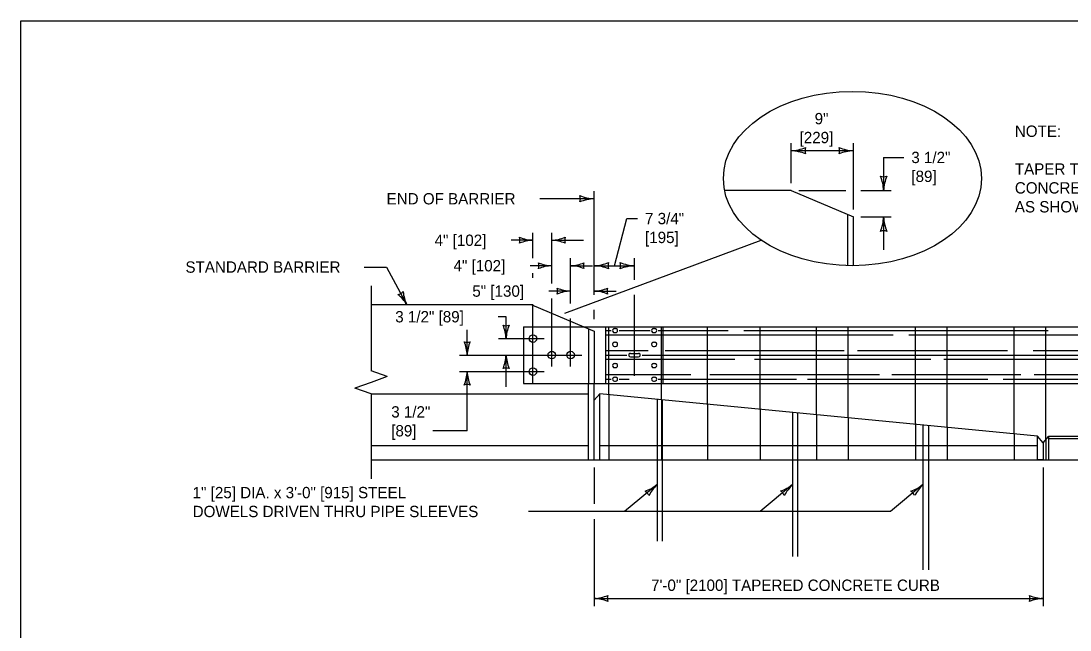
# Model space of a CAD drawing. Extents: x 49991.4 to 50021, y 49987.6 to 50011.4.
# Drawn here: x 49999.38 to 50004.93, y 49995.77 to 49999 of the extents above; entities that cross this region are included whole.
import ezdxf

# ---------------------------------------------------------------- set-up
doc = ezdxf.new("R2010")
doc.units = 0
for name, color, linetype in [('Level 1', 7, 'Continuous'), ('Level 2', 7, 'Continuous'), ('Level 3', 7, 'Continuous'), ('Level 4', 7, 'Continuous'), ('Level 5', 7, 'Continuous'), ('Level 6', 7, 'Continuous')]:
    doc.layers.add(name, color=color, linetype=linetype)

msp = doc.modelspace()

# ---------------------------------------------------------------- linework, layer by layer
at = {"layer": 'Level 1'}
for p, q in [((50003.4584, 49998.1012), (50003.1064, 49998.1012)), ((50003.4584, 49998.1012), (50003.788, 49997.9614)), ((50003.7578, 49997.7035), (50003.7578, 49997.9742)), ((50003.788, 49997.7033), (50003.788, 49997.9613)), ((50002.0873, 49997.4962), (50001.2358, 49997.4962)), ((50002.0873, 49997.4962), (50002.3616, 49997.3798)), ((50002.0422, 49997.3798), (50006.0658, 49997.3798)), ((50002.0422, 49997.3798), (50002.0422, 49997.0804)), ((50002.4775, 49997.0804), (50002.4775, 49997.3798)), ((50002.4775, 49997.3599), (50002.5055, 49997.3599)), ((50002.524, 49997.3709), (50002.5293, 49997.3709)), ((50002.5479, 49997.3599), (50002.7123, 49997.3599)), ((50002.7308, 49997.3709), (50002.7361, 49997.3709)), ((50002.7547, 49997.3599), (50003.1251, 49997.3599)), ((50003.209, 49997.3599), (50004.8191, 49997.3599)), ((50002.4775, 49997.3382), (50003.9979, 49997.3382)), ((50002.524, 49997.3489), (50002.5293, 49997.3489)), ((50002.7308, 49997.3489), (50002.7361, 49997.3489)), ((50004.082, 49997.3382), (50005.5076, 49997.3382)), ((50002.4775, 49997.2548), (50002.7015, 49997.2548)), ((50002.524, 49997.2982), (50002.5293, 49997.2982)), ((50002.524, 49997.2762), (50002.5293, 49997.2762)), ((50002.7308, 49997.2982), (50002.7361, 49997.2982)), ((50002.7308, 49997.2762), (50002.7361, 49997.2762)), ((50002.792, 49997.2548), (50003.7392, 49997.2548)), ((50003.8104, 49997.2548), (50004.6025, 49997.2548)), ((50004.7382, 49997.2548), (50005.7177, 49997.2548)), ((50002.4775, 49997.2301), (50002.5891, 49997.2301)), ((50002.4775, 49997.2083), (50003.1606, 49997.2083)), ((50002.6083, 49997.2392), (50002.6509, 49997.2392)), ((50002.6083, 49997.221), (50002.6509, 49997.221)), ((50002.67, 49997.2301), (50006.0658, 49997.2301)), ((50003.2639, 49997.2083), (50004.1983, 49997.2083)), ((50004.2662, 49997.2083), (50005.388, 49997.2083)), ((50002.524, 49997.1856), (50002.5293, 49997.1856)), ((50002.524, 49997.1636), (50002.5293, 49997.1636)), ((50002.7308, 49997.1856), (50002.7361, 49997.1856)), ((50002.7308, 49997.1636), (50002.7361, 49997.1636)), ((50002.4775, 49997.1274), (50002.9278, 49997.1274)), ((50002.4775, 49997.1026), (50002.5055, 49997.1026)), ((50002.524, 49997.1136), (50002.5293, 49997.1136)), ((50002.524, 49997.0916), (50002.5293, 49997.0916)), ((50002.5479, 49997.1026), (50002.6013, 49997.1026)), ((50002.7308, 49997.1136), (50002.7361, 49997.1136)), ((50002.7308, 49997.0916), (50002.7361, 49997.0916)), ((50002.7547, 49997.1026), (50003.4871, 49997.1026)), ((50003.0281, 49997.1274), (50003.9268, 49997.1274)), ((50003.5452, 49997.1026), (50004.499, 49997.1026)), ((50003.9914, 49997.1274), (50004.6736, 49997.1274)), ((50004.5798, 49997.1026), (50005.401, 49997.1026)), ((50004.7446, 49997.1274), (50006.0658, 49997.1274)), ((50002.0422, 49997.0804), (50006.0658, 49997.0804)), ((50002.3867, 49996.6755), (50002.3867, 49997.0804)), ((50002.4169, 49996.6755), (50002.4169, 49997.0804)), ((50002.4935, 49997.0206), (50002.4935, 49997.0804)), ((50002.7722, 49996.9935), (50002.7722, 49997.0804)), ((50003.016, 49996.9698), (50003.016, 49997.0804)), ((50003.2946, 49996.9428), (50003.2946, 49997.0804)), ((50003.593, 49996.9138), (50003.593, 49997.0804)), ((50003.7603, 49996.8976), (50003.7603, 49997.0804)), ((50004.1159, 49996.863), (50004.1159, 49997.0804)), ((50004.2832, 49996.8468), (50004.2832, 49997.0804)), ((50004.6388, 49996.8123), (50004.6388, 49997.0804)), ((50004.8061, 49996.7825), (50004.8061, 49997.0804)), ((50001.2358, 49997.0251), (50002.3867, 49997.0251)), ((50002.4169, 49996.9911), (50002.4468, 49997.0251)), ((50002.4468, 49996.6755), (50002.4468, 49997.0251)), ((50004.7611, 49996.8004), (50002.4468, 49997.0251)), ((50001.2358, 49996.7505), (50002.3867, 49996.7505)), ((50002.4468, 49996.7505), (50004.7611, 49996.7505)), ((50004.7911, 49996.7647), (50004.7611, 49996.8004)), ((50004.7911, 49996.7647), (50004.8211, 49996.8004)), ((50004.7911, 49996.7647), (50004.7911, 49996.6755)), ((50004.8211, 49996.6755), (50004.8211, 49996.8004)), ((50004.8211, 49996.8004), (50006.0658, 49996.8004)), ((50004.8211, 49996.7886), (50006.0658, 49996.7886)), ((50001.2358, 49996.6755), (50006.0658, 49996.6755))]:
    msp.add_line(p, q, dxfattribs=at)
msp.add_lwpolyline([(49999.3835, 49998.9992), (50016.7501, 49998.9992), (50016.7501, 49987.7988), (49999.3835, 49987.7988)], close=True, dxfattribs=at)
msp.add_lwpolyline([(50004.7911, 49996.6755), (50004.7611, 49996.6755), (50004.7611, 49996.8004)], dxfattribs=at)
for centre in [(50002.092, 49997.3174), (50002.1921, 49997.2301), (50002.2915, 49997.2301), (50002.092, 49997.1425)]:
    msp.add_circle(centre, 0.02, dxfattribs=at)
for centre, major_axis, ratio, start_param, end_param in [((50002.524, 49997.3599), (0.011, 0), 0.998676, 1.570796, 4.712389), ((50002.5293, 49997.3599), (0.011, 0), 0.998676, 4.712389, 7.853982), ((50002.7308, 49997.3599), (0.011, 0), 0.998676, 1.570796, 4.712389), ((50002.7361, 49997.3599), (0.011, 0), 0.998676, 4.712389, 7.853982), ((50002.524, 49997.2872), (0.011, 0), 0.998676, 1.570796, 4.712389), ((50002.5293, 49997.2872), (0.011, 0), 0.998676, 4.712389, 7.853982), ((50002.7308, 49997.2872), (0.011, 0), 0.998676, 1.570796, 4.712389), ((50002.7361, 49997.2872), (0.011, 0), 0.998676, 4.712389, 7.853982), ((50002.6083, 49997.2301), (0.00923, 0), 0.988923, 1.570796, 4.712389), ((50002.6509, 49997.2301), (0.00917, 0), 0.995211, 4.712389, 7.853982), ((50002.524, 49997.1746), (0.011, 0), 0.998676, 1.570796, 4.712389), ((50002.5293, 49997.1746), (0.011, 0), 0.998676, 4.712389, 7.853982), ((50002.7308, 49997.1746), (0.011, 0), 0.998676, 1.570796, 4.712389), ((50002.7361, 49997.1746), (0.011, 0), 0.998676, 4.712389, 7.853982), ((50002.524, 49997.1026), (0.011, 0), 0.998676, 1.570796, 4.712389), ((50002.5293, 49997.1026), (0.011, 0), 0.998676, 4.712389, 7.853982), ((50002.7308, 49997.1026), (0.011, 0), 0.998676, 1.570796, 4.712389), ((50002.7361, 49997.1026), (0.011, 0), 0.998676, 4.712389, 7.853982)]:
    msp.add_ellipse(centre, major_axis=major_axis, ratio=ratio, start_param=start_param, end_param=end_param, dxfattribs=at)
at = {"layer": 'Level 3'}
for p, q in [((50003.4584, 49998.1412), (50003.4584, 49998.3521)), ((50003.788, 49998.3121), (50003.4584, 49998.3121)), ((50003.788, 49998.0014), (50003.788, 49998.3521)), ((50003.9479, 49998.2766), (50003.9479, 49998.1012)), ((50003.9479, 49998.2766), (50004.0545, 49998.2766)), ((50002.4165, 49997.5495), (50002.4165, 49998.0978)), ((50003.4984, 49998.1012), (50003.748, 49998.1012)), ((50003.828, 49998.1012), (50003.9879, 49998.1012)), ((50002.4165, 49998.0578), (50002.128, 49998.0578)), ((50002.5231, 49997.7034), (50002.5888, 49997.9531)), ((50002.5888, 49997.9531), (50002.6453, 49997.9531)), ((50003.828, 49997.9613), (50003.9879, 49997.9613)), ((50003.9479, 49997.9613), (50003.9479, 49997.7879)), ((50002.092, 49997.838), (50001.9771, 49997.838)), ((50002.1921, 49997.838), (50002.3605, 49997.838)), ((50002.2619, 49997.452), (50003.2998, 49997.8384)), ((50001.1985, 49997.6962), (50001.3181, 49997.6962)), ((50001.3181, 49997.6962), (50001.4253, 49997.4962)), ((50002.1921, 49997.7033), (50002.0771, 49997.7033)), ((50002.2915, 49997.7034), (50002.4066, 49997.7034)), ((50002.4165, 49997.7034), (50002.6297, 49997.7034)), ((50002.2915, 49997.569), (50002.1766, 49997.569)), ((50002.4165, 49997.569), (50002.5321, 49997.569)), ((50001.9503, 49997.4331), (50001.9084, 49997.4331)), ((50001.9503, 49997.3174), (50001.9503, 49997.4331)), ((50002.4165, 49997.4198), (50002.4165, 49997.4695)), ((50001.7443, 49997.2301), (50001.7443, 49997.3631)), ((50001.9503, 49997.0617), (50001.9503, 49997.2301)), ((50001.7443, 49996.8294), (50001.7443, 49997.1425)), ((50001.7441, 49996.8294), (50001.562, 49996.8294)), ((50002.4169, 49996.6355), (50002.4169, 49996.442)), ((50004.7911, 49996.6355), (50004.7911, 49995.9015)), ((50002.7494, 49996.5442), (50002.5776, 49996.402)), ((50003.4665, 49996.5442), (50003.2947, 49996.402)), ((50004.1559, 49996.5442), (50003.984, 49996.402)), ((50003.984, 49996.402), (50002.068, 49996.402)), ((50002.4169, 49996.362), (50002.4169, 49995.9015)), ((50002.4169, 49995.9415), (50004.7911, 49995.9415))]:
    msp.add_line(p, q, dxfattribs=at)
for centre, radius, start, end in [((50003.4469, 49998.5448), 0.233, 272.8273, 292.0772), ((50003.4492, 49998.09), 0.2223, 67.456, 87.6395), ((50003.5866, 49998.3121), 0.0548, 162.1388, 197.8612), ((50003.7971, 49998.5343), 0.2223, 247.456, 267.6395), ((50003.6598, 49998.3121), 0.0548, 342.1388, 17.8612), ((50003.7995, 49998.0794), 0.233, 92.8273, 112.0772), ((50003.9479, 49998.2294), 0.0548, 252.1388, 287.8612), ((50003.7152, 49998.0897), 0.233, 2.8273, 22.0772), ((50004.17, 49998.0921), 0.2223, 157.456, 177.6395), ((50002.4257, 49998.2799), 0.2223, 247.456, 267.6395), ((50002.2883, 49998.0578), 0.0548, 342.1388, 17.8612), ((50002.428, 49997.8251), 0.233, 92.8273, 112.0772), ((50003.7257, 49997.9705), 0.2223, 337.456, 357.6395), ((50004.1806, 49997.9728), 0.233, 182.8273, 202.0772), ((50003.9479, 49997.8331), 0.0548, 72.1388, 107.8612), ((50002.1005, 49998.0449), 0.2071, 247.456, 267.6395), ((50001.9726, 49997.838), 0.051, 342.1388, 17.8612), ((50002.1027, 49997.6212), 0.2171, 92.8273, 112.0772), ((50002.1814, 49998.0548), 0.2171, 272.8273, 292.0772), ((50002.1836, 49997.6311), 0.2071, 67.456, 87.6395), ((50002.3115, 49997.838), 0.051, 162.1388, 197.8612), ((50002.2006, 49997.9102), 0.2071, 247.456, 267.6395), ((50002.0727, 49997.7033), 0.051, 342.1388, 17.8612), ((50002.2028, 49997.4865), 0.2171, 92.8273, 112.0772), ((50002.2808, 49997.9202), 0.2171, 272.8273, 292.0772), ((50002.283, 49997.4965), 0.2071, 67.456, 87.6395), ((50002.4109, 49997.7034), 0.051, 162.1388, 197.8612), ((50002.405, 49997.9361), 0.233, 272.8273, 292.0772), ((50002.4073, 49997.4813), 0.2223, 67.456, 87.6395), ((50002.5447, 49997.7034), 0.0548, 162.1388, 197.8612), ((50002.6389, 49997.9255), 0.2223, 247.456, 267.6395), ((50002.5015, 49997.7034), 0.0548, 342.1388, 17.8612), ((50002.6412, 49997.4707), 0.233, 92.8273, 112.0772), ((50002.3, 49997.7759), 0.2071, 247.456, 267.6395), ((50002.1721, 49997.569), 0.051, 342.1388, 17.8612), ((50002.4058, 49997.7858), 0.2171, 272.8273, 292.0772), ((50002.5359, 49997.569), 0.051, 162.1388, 197.8612), ((50001.3689, 49997.6015), 0.051, 280.3425, 316.0649), ((50001.2394, 49997.3843), 0.2171, 31.031, 50.2809), ((50001.6117, 49997.5865), 0.2071, 185.6597, 205.8432), ((50002.3022, 49997.3522), 0.2171, 92.8273, 112.0772), ((50002.408, 49997.3621), 0.2071, 67.456, 87.6395), ((50001.9503, 49997.4368), 0.051, 252.1388, 287.8612), ((50001.7335, 49997.3067), 0.2171, 2.8273, 22.0772), ((50002.1572, 49997.3089), 0.2071, 157.456, 177.6395), ((50001.7443, 49997.3495), 0.051, 252.1388, 287.8612), ((50001.5275, 49997.2194), 0.2171, 2.8273, 22.0772), ((50001.9512, 49997.2216), 0.2071, 157.456, 177.6395), ((50001.7433, 49997.2386), 0.2071, 337.456, 357.6395), ((50002.1671, 49997.2408), 0.2171, 182.8273, 202.0772), ((50001.5374, 49997.151), 0.2071, 337.456, 357.6395), ((50001.9611, 49997.1532), 0.2171, 182.8273, 202.0772), ((50001.9503, 49997.1107), 0.051, 72.1388, 107.8612), ((50001.7443, 49997.0231), 0.051, 72.1388, 107.8612), ((50002.6217, 49996.7072), 0.2071, 287.8812, 308.0647), ((50002.8981, 49996.3861), 0.2171, 133.2525, 152.5023), ((50003.3405, 49996.7086), 0.2071, 287.2811, 307.4646), ((50003.6136, 49996.3846), 0.2171, 132.6524, 151.9023), ((50004.0282, 49996.7072), 0.2071, 287.8709, 308.0544), ((50004.3046, 49996.3861), 0.2171, 133.2422, 152.492), ((50002.6585, 49996.4667), 0.051, 22.564, 58.2863), ((50003.3748, 49996.4677), 0.051, 21.9639, 57.6863), ((50004.0649, 49996.4667), 0.051, 22.5537, 58.2761), ((50002.4062, 49996.1583), 0.2171, 272.8273, 292.0772), ((50002.4084, 49995.7346), 0.2071, 67.456, 87.6395), ((50002.5363, 49995.9415), 0.051, 162.1388, 197.8612), ((50004.7996, 49996.1484), 0.2071, 247.456, 267.6395), ((50004.6716, 49995.9415), 0.051, 342.1388, 17.8612), ((50004.8018, 49995.7247), 0.2171, 92.8273, 112.0772)]:
    msp.add_arc(centre, radius, start, end, dxfattribs=at)
msp.add_ellipse((50003.7824, 49998.1648), major_axis=(0.6825, 0), ratio=0.676333, dxfattribs=at)
at = {"layer": 'Level 4'}
for p, q in [((50002.3616, 49997.3798), (50002.4169, 49997.3563)), ((50002.3867, 49997.3691), (50002.3867, 49997.0804)), ((50002.4935, 49997.0804), (50002.4935, 49997.3798)), ((50002.7722, 49997.0804), (50002.7722, 49997.3798)), ((50002.7817, 49997.0804), (50002.7817, 49997.3798)), ((50003.016, 49997.0804), (50003.016, 49997.3798)), ((50003.2946, 49997.0804), (50003.2946, 49997.3798)), ((50003.593, 49997.0804), (50003.593, 49997.3798)), ((50003.7603, 49997.0804), (50003.7603, 49997.3798)), ((50004.1159, 49997.0804), (50004.1159, 49997.3798)), ((50004.2832, 49997.0804), (50004.2832, 49997.3798)), ((50004.6388, 49997.0804), (50004.6388, 49997.3798)), ((50004.8061, 49997.0804), (50004.8061, 49997.3798)), ((50002.4169, 49997.3563), (50002.4169, 49997.0804)), ((50002.4935, 49997.0206), (50002.4935, 49996.6755)), ((50002.7494, 49996.9957), (50002.7494, 49996.244)), ((50002.7722, 49996.9935), (50002.7722, 49996.6755)), ((50002.7768, 49996.9931), (50002.7768, 49996.244)), ((50003.016, 49996.9698), (50003.016, 49996.6755)), ((50003.2946, 49996.9428), (50003.2946, 49996.6755)), ((50003.4665, 49996.9261), (50003.4665, 49996.1642)), ((50003.4925, 49996.9236), (50003.4925, 49996.1642)), ((50003.593, 49996.9138), (50003.593, 49996.6755)), ((50003.7603, 49996.8976), (50003.7603, 49996.6755)), ((50004.1159, 49996.863), (50004.1159, 49996.6755)), ((50004.1559, 49996.8592), (50004.1559, 49996.0937)), ((50004.1853, 49996.8563), (50004.1853, 49996.0937)), ((50004.2832, 49996.8468), (50004.2832, 49996.6755)), ((50004.6388, 49996.8123), (50004.6388, 49996.6755)), ((50004.8061, 49996.7825), (50004.8061, 49996.6755))]:
    msp.add_line(p, q, dxfattribs=at)
at = {"layer": 'Level 5'}
for p, q in [((50002.092, 49997.7433), (50002.092, 49997.878)), ((50002.1921, 49997.609), (50002.1921, 49997.878)), ((50002.2915, 49997.503), (50002.2915, 49997.7434)), ((50002.6297, 49997.6289), (50002.6297, 49997.7434)), ((50002.092, 49997.6391), (50002.092, 49997.6633)), ((50002.1921, 49997.1701), (50002.1921, 49997.529)), ((50002.6297, 49997.1198), (50002.6297, 49997.5489)), ((50002.092, 49997.0825), (50002.092, 49997.499)), ((50002.2915, 49997.1701), (50002.2915, 49997.423)), ((50001.9103, 49997.3174), (50002.152, 49997.3174)), ((50001.7043, 49997.2301), (50002.3515, 49997.2301)), ((50001.7043, 49997.1425), (50002.152, 49997.1425))]:
    msp.add_line(p, q, dxfattribs=at)
at = {"layer": 'Level 6'}
for p, q in [((50001.2358, 49997.5962), (50001.2358, 49997.1462)), ((50001.3209, 49997.116), (50001.2358, 49997.1462)), ((50001.2358, 49997.0858), (50001.1507, 49997.0556)), ((50001.3209, 49997.116), (50001.2358, 49997.0858)), ((50001.2358, 49997.0255), (50001.1507, 49997.0556)), ((50001.2358, 49997.0255), (50001.2358, 49996.5755))]:
    msp.add_line(p, q, dxfattribs=at)

# ---------------------------------------------------------------- texts
at = {"layer": 'Level 2'}
for s, p in [('9"', (50003.5829, 49998.4521)), ('[229]', (50003.5031, 49998.3521)), ('NOTE:', (50004.642, 49998.3854)), ('3 1/2"', (50004.0945, 49998.2466)), ('[89]', (50004.0945, 49998.1466)), ('TAPER THE END OF THE', (50004.642, 49998.1854)), ('CONCRETE BARRIER RAIL', (50004.642, 49998.0854)), ('END OF BARRIER', (50001.3179, 49998.0278)), ('AS SHOWN.', (50004.642, 49997.9854)), ('7 3/4"', (50002.6853, 49997.9231)), ('4" [102]', (50001.5721, 49997.808)), ('[195]', (50002.6853, 49997.8231)), ('STANDARD BARRIER', (50000.2537, 49997.6662)), ('4" [102]', (50001.6721, 49997.6733)), ('5" [130]', (50001.7716, 49997.539)), ('3 1/2" [89]', (50001.3638, 49997.4031)), ('3 1/2"', (50001.3425, 49996.8994)), ('[89]', (50001.3425, 49996.7994)), ('1" [25] DIA. x 3\'-0" [915] STEEL', (50000.2918, 49996.472)), ('DOWELS DRIVEN THRU PIPE SLEEVES', (50000.2918, 49996.372)), ('7\'-0" [2100] TAPERED CONCRETE CURB', (50002.7173, 49995.9815))]:
    msp.add_text(s, height=0.06, dxfattribs=at).set_placement(p)

doc.saveas('drawing.dxf')
